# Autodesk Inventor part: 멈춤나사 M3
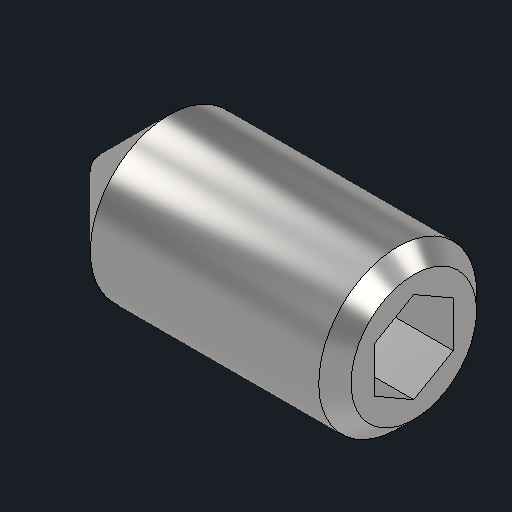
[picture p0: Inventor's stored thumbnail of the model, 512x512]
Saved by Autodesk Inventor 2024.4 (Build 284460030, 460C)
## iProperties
Created: 2026-08
Part Number: 멈춤나사 M3
Material: 강철, 연강
Description: 6각 소켓 머리 없는 멈춤 나사
Document SubType Name: Modeling
Designer: user
Density: 7.85 g/cm^3
Appearance: 기본값
Author: jhkim
Sending System: Autodesk Inventor 2027
Preprocessor: ST-DEVELOPER v20.1
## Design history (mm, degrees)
feature "Solid1"
node "솔리드1"
